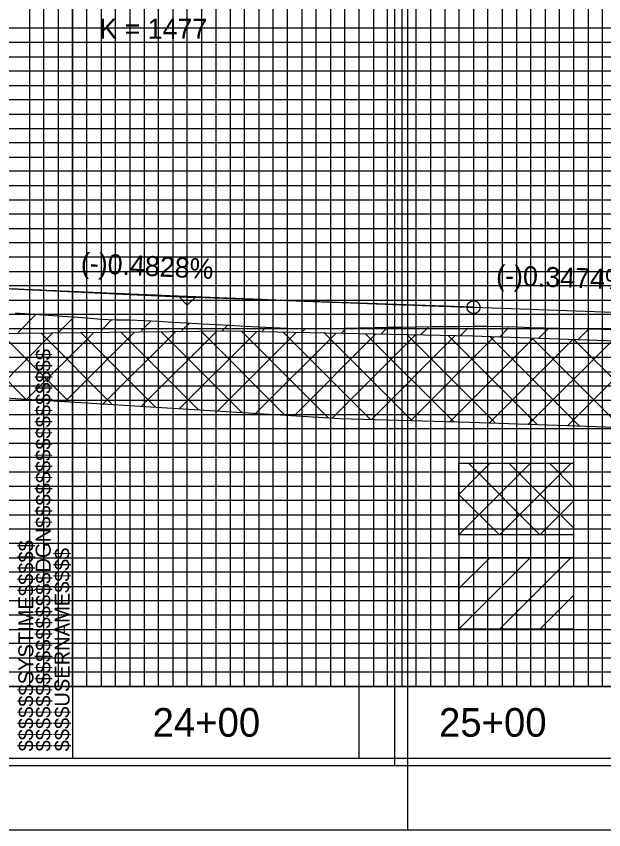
# Model space of a CAD drawing. Extents: x 2345490 to 2436403, y 465165 to 573888.
# Drawn here: x 2383070.5 to 2383275.6, y 491453 to 491737.1 of the extents above; entities that cross this region are included whole.
import ezdxf

# ---------------------------------------------------------------- set-up
doc = ezdxf.new("R2010")
doc.units = 0
for name, color, linetype in [('Old_Level_1', 7, 'Continuous'), ('Old_Level_18', 7, 'Continuous'), ('Old_Level_2', 7, 'Continuous'), ('Old_Level_40', 7, 'Continuous'), ('Old_Level_41', 7, 'Continuous'), ('Old_Level_42', 7, 'Continuous'), ('Old_Level_43', 7, 'Continuous'), ('Old_Level_5', 7, 'Continuous'), ('Old_Level_50', 7, 'Continuous'), ('Old_Level_51', 7, 'Continuous'), ('Old_Level_62', 7, 'Continuous'), ('Old_Level_63', 7, 'Continuous'), ('Prop Vertical Profile Grade', 7, 'Continuous')]:
    doc.layers.add(name, color=color, linetype=linetype)

msp = doc.modelspace()

# ---------------------------------------------------------------- linework, layer by layer
at = {"layer": 'Old_Level_1'}
for points in [[(2383070.125, 491633.55625), (2383075.125, 491633.1875), (2383080.125, 491632.81875), (2383085.125, 491632.45), (2383090.125, 491632.08125), (2383095.125, 491631.7125), (2383100.125, 491631.34375), (2383105.125, 491631.0885), (2383110.125, 491631.014), (2383115.125, 491630.83225), (2383120.125, 491630.5555), (2383125.125, 491630.27875), (2383130.125, 491630.002), (2383135.125, 491629.72525), (2383140.125, 491629.4485), (2383145.125, 491629.172), (2383150.125, 491628.89525), (2383155.125, 491628.6185), (2383160.125, 491628.34175), (2383165.125, 491628.175), (2383170.125, 491628.07075), (2383175.125, 491628.00875), (2383180.125, 491628.09875), (2383185.125, 491628.189), (2383190.125, 491628.27925), (2383195.125, 491628.36925), (2383200.125, 491628.4595), (2383205.125, 491628.5495), (2383210.125, 491628.63975), (2383215.125, 491628.73), (2383220.125, 491628.776), (2383225.125, 491628.7905), (2383230.125, 491628.805), (2383235.125, 491628.81925), (2383240.125, 491628.71075)], [(2383240.125, 491628.71075), (2383245.125, 491628.57625), (2383250.125, 491628.4415), (2383255.125, 491628.307), (2383260.125, 491628.17225), (2383265.125, 491628.03775), (2383270.125, 491627.903), (2383275.125, 491627.81575), (2383280.125, 491627.77375)]]:
    msp.add_lwpolyline(points, dxfattribs=at)
at = {"layer": 'Old_Level_18'}
msp.add_line((2383090.125, 491477.95225), (2383090.125, 491477.95225), dxfattribs=at)
msp.add_line((2383090.125, 491477.95225), (2383090.125, 491477.95225), dxfattribs=at)
for points in [[(2383190.125, 492527.95225), (2381690.125, 492527.95225), (2381690.125, 491477.95225), (2383190.125, 491477.95225)], [(2384590.125, 492527.95225), (2383090.125, 492527.95225), (2383090.125, 491477.95225), (2384590.125, 491477.95225)]]:
    msp.add_lwpolyline(points, close=True, dxfattribs=at)
at = {"layer": 'Old_Level_2'}
for p, q in [((2383030.125, 491643.77989), (2383127.3782, 491639.0849)), ((2383127.3782, 491639.0849), (2383132.87334, 491638.85683)), ((2383130.125, 491636.2023), (2383127.3782, 491639.0849)), ((2383132.87334, 491638.85683), (2383130.125, 491636.2023)), ((2383230.125, 491635.47869), (2383132.87334, 491638.85683))]:
    msp.add_line(p, q, dxfattribs=at)
msp.add_circle((2383230.125, 491635.47869), 2.25, dxfattribs=at)
at = {"layer": 'Old_Level_40'}
msp.add_line((2383090.125, 491477.95225), (2383090.125, 491477.95225), dxfattribs=at)
msp.add_line((2383090.125, 491477.95225), (2383090.125, 491477.95225), dxfattribs=at)
msp.add_line((2383090.125, 491477.95225), (2383090.125, 491477.95225), dxfattribs=at)
msp.add_line((2383090.125, 491477.95225), (2383090.125, 491477.95225), dxfattribs=at)
at = {"layer": 'Old_Level_41'}
for p, q in [((2383190.125, 491502.95225), (2381690.125, 491502.95225)), ((2384590.125, 491502.95225), (2383090.125, 491502.95225))]:
    msp.add_line(p, q, dxfattribs=at)
for points in [[(2383090.125, 492527.95225), (2383140.125, 492527.95225), (2383140.125, 491502.95225), (2383190.125, 491502.95225), (2383190.125, 492527.95225), (2383240.125, 492527.95225), (2383240.125, 491502.95225), (2383290.125, 491502.95225), (2383290.125, 492527.95225), (2383340.125, 492527.95225), (2383340.125, 491502.95225), (2383390.125, 491502.95225), (2383390.125, 492527.95225), (2383440.125, 492527.95225), (2383440.125, 491502.95225), (2383490.125, 491502.95225), (2383490.125, 492527.95225), (2383540.125, 492527.95225), (2383540.125, 491502.95225), (2383590.125, 491502.95225), (2383590.125, 492527.95225), (2383640.125, 492527.95225), (2383640.125, 491502.95225), (2383690.125, 491502.95225)], [(2383165.125, 491502.95225), (2383165.125, 492527.95225), (2383215.125, 492527.95225), (2383215.125, 491502.95225), (2383265.125, 491502.95225), (2383265.125, 492527.95225), (2383315.125, 492527.95225), (2383315.125, 491502.95225), (2383365.125, 491502.95225), (2383365.125, 492527.95225), (2383415.125, 492527.95225), (2383415.125, 491502.95225), (2383465.125, 491502.95225), (2383465.125, 492527.95225), (2383515.125, 492527.95225), (2383515.125, 491502.95225), (2383565.125, 491502.95225), (2383565.125, 492527.95225), (2383615.125, 492527.95225), (2383615.125, 491502.95225), (2383665.125, 491502.95225), (2383665.125, 492527.95225), (2383715.125, 492527.95225)], [(2383115.125, 492390.40225), (2383115.125, 491502.95225)], [(2383190.125, 491727.95225), (2381690.125, 491727.95225), (2381690.125, 491677.95225), (2383190.125, 491677.95225)], [(2384590.125, 491727.95225), (2383090.125, 491727.95225), (2383090.125, 491677.95225), (2384590.125, 491677.95225)], [(2383190.125, 491627.95225), (2381690.125, 491627.95225), (2381690.125, 491577.95225), (2383190.125, 491577.95225)], [(2384590.125, 491627.95225), (2383090.125, 491627.95225), (2383090.125, 491577.95225), (2384590.125, 491577.95225)], [(2383190.125, 491552.95225), (2381690.125, 491552.95225), (2381690.125, 491602.95225), (2383190.125, 491602.95225)], [(2384590.125, 491552.95225), (2383090.125, 491552.95225), (2383090.125, 491602.95225), (2384590.125, 491602.95225)], [(2383190.125, 491527.95225), (2381690.125, 491527.95225)], [(2384590.125, 491527.95225), (2383090.125, 491527.95225)], [(2383127.625, 491477.95225), (2383127.625, 491477.95225)]]:
    msp.add_lwpolyline(points, dxfattribs=at)
at = {"layer": 'Old_Level_42'}
for points in [[(2383040.125, 492390.40225), (2383040.125, 491502.95225), (2383090.125, 491502.95225), (2383090.125, 492390.40225)], [(2383140.125, 492390.40225), (2383140.125, 491502.95225), (2383190.125, 491502.95225)], [(2383190.125, 491652.95225), (2381690.125, 491652.95225), (2381690.125, 491702.95225), (2383190.125, 491702.95225)], [(2384590.125, 491652.95225), (2383090.125, 491652.95225), (2383090.125, 491702.95225), (2384590.125, 491702.95225)]]:
    msp.add_lwpolyline(points, dxfattribs=at)
at = {"layer": 'Old_Level_43'}
for points in [[(2383145.125, 492527.95225), (2383145.125, 491502.95225), (2383150.125, 491502.95225), (2383150.125, 492527.95225)], [(2383155.125, 492527.95225), (2383155.125, 491502.95225), (2383160.125, 491502.95225), (2383160.125, 492527.95225)], [(2383170.125, 492527.95225), (2383170.125, 491502.95225), (2383175.125, 491502.95225), (2383175.125, 492527.95225)], [(2383180.125, 492527.95225), (2383180.125, 491502.95225), (2383185.125, 491502.95225), (2383185.125, 492527.95225)], [(2383195.125, 492527.95225), (2383195.125, 491502.95225), (2383200.125, 491502.95225), (2383200.125, 492527.95225)], [(2383205.125, 492527.95225), (2383205.125, 491502.95225), (2383210.125, 491502.95225), (2383210.125, 492527.95225)], [(2383220.125, 492527.95225), (2383220.125, 491502.95225), (2383225.125, 491502.95225), (2383225.125, 492527.95225)], [(2383230.125, 492527.95225), (2383230.125, 491502.95225), (2383235.125, 491502.95225), (2383235.125, 492527.95225)], [(2383245.125, 492527.95225), (2383245.125, 491502.95225), (2383250.125, 491502.95225), (2383250.125, 492527.95225)], [(2383255.125, 492527.95225), (2383255.125, 491502.95225), (2383260.125, 491502.95225), (2383260.125, 492527.95225)], [(2383270.125, 492527.95225), (2383270.125, 491502.95225), (2383275.125, 491502.95225), (2383275.125, 492527.95225)], [(2383075.125, 492390.40225), (2383075.125, 491502.95225)], [(2383075.125, 491502.95225), (2383080.125, 491502.95225), (2383080.125, 492390.40225)], [(2383085.125, 492390.40225), (2383085.125, 491502.95225), (2383095.125, 491502.95225), (2383095.125, 492390.40225)], [(2383100.125, 492390.40225), (2383100.125, 491502.95225), (2383105.125, 491502.95225), (2383105.125, 492390.40225)], [(2383110.125, 492390.40225), (2383110.125, 491502.95225), (2383120.125, 491502.95225), (2383120.125, 492390.40225)], [(2383125.125, 492390.40225), (2383125.125, 491502.95225), (2383130.125, 491502.95225), (2383130.125, 492390.40225)], [(2383135.125, 492390.40225), (2383135.125, 491502.95225), (2383145.125, 491502.95225)], [(2383140.125, 491732.95225), (2381740.125, 491732.95225), (2381740.125, 491722.95225), (2383140.125, 491722.95225)], [(2384540.125, 491732.95225), (2383140.125, 491732.95225), (2383140.125, 491722.95225), (2384540.125, 491722.95225)], [(2383140.125, 491717.95225), (2381740.125, 491717.95225), (2381740.125, 491712.95225), (2383140.125, 491712.95225)], [(2384540.125, 491717.95225), (2383140.125, 491717.95225), (2383140.125, 491712.95225), (2384540.125, 491712.95225)], [(2383140.125, 491707.95225), (2381740.125, 491707.95225)], [(2384540.125, 491707.95225), (2383140.125, 491707.95225)], [(2381740.125, 491697.95225), (2383140.125, 491697.95225)], [(2383140.125, 491697.95225), (2384540.125, 491697.95225)], [(2383140.125, 491692.95225), (2381740.125, 491692.95225), (2381740.125, 491687.95225), (2383140.125, 491687.95225)], [(2384540.125, 491692.95225), (2383140.125, 491692.95225), (2383140.125, 491687.95225), (2384540.125, 491687.95225)], [(2383140.125, 491682.95225), (2381740.125, 491682.95225)], [(2384540.125, 491682.95225), (2383140.125, 491682.95225)], [(2381740.125, 491672.95225), (2383140.125, 491672.95225)], [(2383140.125, 491672.95225), (2384540.125, 491672.95225)], [(2383140.125, 491667.95225), (2381740.125, 491667.95225), (2381740.125, 491662.95225), (2383140.125, 491662.95225)], [(2384540.125, 491667.95225), (2383140.125, 491667.95225), (2383140.125, 491662.95225), (2384540.125, 491662.95225)], [(2383140.125, 491657.95225), (2381740.125, 491657.95225), (2381740.125, 491647.95225), (2383140.125, 491647.95225)], [(2384540.125, 491657.95225), (2383140.125, 491657.95225), (2383140.125, 491647.95225), (2384540.125, 491647.95225)], [(2383140.125, 491642.95225), (2381740.125, 491642.95225), (2381740.125, 491637.95225), (2383140.125, 491637.95225)], [(2384540.125, 491642.95225), (2383140.125, 491642.95225), (2383140.125, 491637.95225), (2384540.125, 491637.95225)], [(2383140.125, 491632.95225), (2381740.125, 491632.95225), (2381740.125, 491622.95225), (2383140.125, 491622.95225)], [(2384540.125, 491632.95225), (2383140.125, 491632.95225), (2383140.125, 491622.95225), (2384540.125, 491622.95225)], [(2383140.125, 491617.95225), (2381740.125, 491617.95225), (2381740.125, 491612.95225), (2383140.125, 491612.95225)], [(2384540.125, 491617.95225), (2383140.125, 491617.95225), (2383140.125, 491612.95225), (2384540.125, 491612.95225)], [(2383140.125, 491607.95225), (2381740.125, 491607.95225), (2381740.125, 491597.95225), (2383140.125, 491597.95225)], [(2384540.125, 491607.95225), (2383140.125, 491607.95225), (2383140.125, 491597.95225), (2384540.125, 491597.95225)], [(2383140.125, 491592.95225), (2381740.125, 491592.95225), (2381740.125, 491587.95225), (2383140.125, 491587.95225)], [(2384540.125, 491592.95225), (2383140.125, 491592.95225), (2383140.125, 491587.95225), (2384540.125, 491587.95225)], [(2383140.125, 491582.95225), (2381740.125, 491582.95225), (2381740.125, 491572.95225), (2383140.125, 491572.95225)], [(2384540.125, 491582.95225), (2383140.125, 491582.95225), (2383140.125, 491572.95225), (2384540.125, 491572.95225)], [(2383140.125, 491567.95225), (2381740.125, 491567.95225), (2381740.125, 491562.95225), (2383140.125, 491562.95225)], [(2384540.125, 491567.95225), (2383140.125, 491567.95225), (2383140.125, 491562.95225), (2384540.125, 491562.95225)], [(2383140.125, 491557.95225), (2381740.125, 491557.95225), (2381740.125, 491547.95225), (2383140.125, 491547.95225)], [(2384540.125, 491557.95225), (2383140.125, 491557.95225), (2383140.125, 491547.95225), (2384540.125, 491547.95225)], [(2383140.125, 491542.95225), (2381740.125, 491542.95225), (2381740.125, 491537.95225), (2383140.125, 491537.95225)], [(2384540.125, 491542.95225), (2383140.125, 491542.95225), (2383140.125, 491537.95225), (2384540.125, 491537.95225)], [(2383140.125, 491532.95225), (2381740.125, 491532.95225), (2381740.125, 491522.95225), (2383140.125, 491522.95225)], [(2384540.125, 491532.95225), (2383140.125, 491532.95225), (2383140.125, 491522.95225), (2384540.125, 491522.95225)], [(2383140.125, 491517.95225), (2381740.125, 491517.95225), (2381740.125, 491512.95225), (2383140.125, 491512.95225)], [(2384540.125, 491517.95225), (2383140.125, 491517.95225), (2383140.125, 491512.95225), (2384540.125, 491512.95225)], [(2383140.125, 491507.95225), (2381740.125, 491507.95225)], [(2384540.125, 491507.95225), (2383140.125, 491507.95225)]]:
    msp.add_lwpolyline(points, dxfattribs=at)
at = {"layer": 'Old_Level_5'}
for p, q in [((2383070.97543, 491626.56647), (2383077.4445, 491633.03553)), ((2383085.4583, 491626.9072), (2383090.62474, 491632.07364)), ((2383099.94116, 491627.24793), (2383103.86551, 491631.17227)), ((2383114.15767, 491627.3223), (2383117.32488, 491630.48951)), ((2383128.2998, 491627.3223), (2383130.88777, 491629.91027)), ((2383142.44194, 491627.3223), (2383144.2882, 491629.16856)), ((2383156.46194, 491627.20016), (2383157.68883, 491628.42706)), ((2383211.72953, 491625.89922), (2383214.21199, 491628.38168)), ((2383225.44921, 491625.47676), (2383228.28438, 491628.31193)), ((2383239.14736, 491625.03278), (2383242.35677, 491628.24218)), ((2383051.15242, 491626.05368), (2383073.8457, 491603.3604)), ((2383060.86816, 491604.16012), (2383083.11935, 491626.41131)), ((2383065.13809, 491626.21014), (2383088.91656, 491602.43168)), ((2383074.18939, 491603.33922), (2383097.42149, 491626.57132)), ((2383079.12376, 491626.36661), (2383103.98741, 491601.50296)), ((2383087.51063, 491602.51832), (2383111.72364, 491626.73133)), ((2383093.10943, 491626.52308), (2383119.05827, 491600.57424)), ((2383100.83186, 491601.69741), (2383126.02578, 491626.89133)), ((2383107.0951, 491626.67954), (2383134.12913, 491599.64551)), ((2383114.15309, 491600.87651), (2383140.32792, 491627.05134)), ((2383121.08077, 491626.83601), (2383149.19999, 491598.71679)), ((2383127.47432, 491600.05561), (2383154.32117, 491626.90246)), ((2383135.06644, 491626.99248), (2383164.27084, 491597.78807)), ((2383140.79556, 491599.2347), (2383168.1782, 491626.61735)), ((2383149.19308, 491627.00797), (2383179.3417, 491596.85935)), ((2383154.11679, 491598.4138), (2383182.03523, 491626.33224)), ((2383163.63231, 491626.71088), (2383194.02711, 491596.31607)), ((2383167.43802, 491597.5929), (2383195.89225, 491626.04713)), ((2383170.2898, 491626.88589), (2383171.31145, 491627.90754)), ((2383178.07153, 491626.41379), (2383208.56646, 491595.91886)), ((2383180.75925, 491596.772), (2383209.74928, 491625.76202)), ((2383184.11767, 491626.57162), (2383185.45183, 491627.90578)), ((2383192.51075, 491626.1167), (2383223.10581, 491595.52165)), ((2383194.43434, 491596.30495), (2383223.60631, 491625.47691)), ((2383197.94553, 491626.25735), (2383199.81839, 491628.13021)), ((2383206.94998, 491625.81962), (2383237.71045, 491595.05914)), ((2383221.3892, 491625.52253), (2383252.35668, 491594.55505)), ((2383252.81474, 491624.55802), (2383256.38571, 491628.12898)), ((2383266.48212, 491624.08326), (2383270.21991, 491627.82105)), ((2383208.20039, 491595.92886), (2383237.35815, 491625.08662)), ((2383221.96644, 491595.55278), (2383251.02553, 491624.61187)), ((2383235.68467, 491595.12887), (2383264.69291, 491624.13711)), ((2383235.91719, 491625.13667), (2383267.00291, 491594.05095)), ((2383249.35625, 491594.65832), (2383278.3603, 491623.66236)), ((2383250.56825, 491624.62775), (2383281.64915, 491593.54685)), ((2383263.02784, 491594.18776), (2383292.02768, 491623.1876)), ((2383265.21931, 491624.11883), (2383296.29538, 491593.04276)), ((2383225.01945, 491570.10888), (2383235.87731, 491580.96674)), ((2383225.01945, 491555.96674), (2383250.01945, 491580.96674)), ((2383228.30372, 491580.96674), (2383253.30372, 491555.96674)), ((2383239.16158, 491555.96674), (2383264.16158, 491580.96674)), ((2383242.44585, 491580.96674), (2383265.01945, 491558.39315)), ((2383256.58799, 491580.96674), (2383265.01945, 491572.53529)), ((2383225.01945, 491570.10888), (2383239.16158, 491555.96674)), ((2383253.30372, 491555.96674), (2383265.01945, 491567.68247)), ((2383225.01945, 491555.96674), (2383225.01945, 491555.96674)), ((2383225.01945, 491537.19493), (2383235.87731, 491548.05279)), ((2383225.01945, 491523.05279), (2383250.01945, 491548.05279)), ((2383239.16158, 491523.05279), (2383264.16158, 491548.05279)), ((2383253.30372, 491523.05279), (2383265.01945, 491534.76852)), ((2383225.01945, 491523.05279), (2383225.01945, 491523.05279))]:
    msp.add_line(p, q, dxfattribs=at)
msp.add_lwpolyline([(2382934.83795, 491597.73858), (2383032.62499, 491604.97631), (2383047.62499, 491604.97631), (2383183.48336, 491596.60422), (2383228.76328, 491595.36718), (2383526.4582, 491585.12107), (2383527.68499, 491615.09754), (2383504.06829, 491615.8222), (2383229.77783, 491625.35003), (2383144.70493, 491627.10041), (2383030.41861, 491625.82181), (2382939.67787, 491624.39126), (2382935.12499, 491599.31925)], dxfattribs=at)
for points in [[(2383225.01945, 491580.96674), (2383265.01945, 491580.96674), (2383265.01945, 491555.96674), (2383225.01945, 491555.96674)], [(2383225.01945, 491548.05279), (2383265.01945, 491548.05279), (2383265.01945, 491523.05279), (2383225.01945, 491523.05279)]]:
    msp.add_lwpolyline(points, close=True, dxfattribs=at)
at = {"layer": 'Old_Level_50'}
for points in [[(2383202.625, 492530.50225), (2381536.125, 492530.50225), (2381536.125, 491475.40225), (2383202.625, 491475.40225)], [(2384602.625, 492530.50225), (2382936.125, 492530.50225), (2382936.125, 491475.40225), (2384602.625, 491475.40225)]]:
    msp.add_lwpolyline(points, close=True, dxfattribs=at)
at = {"layer": 'Old_Level_51'}
for points in [[(2383207.125, 492552.95225), (2381523.125, 492552.95225), (2381523.125, 491452.95225), (2383207.125, 491452.95225)], [(2384607.125, 492552.95225), (2382923.125, 492552.95225), (2382923.125, 491452.95225), (2384607.125, 491452.95225)]]:
    msp.add_lwpolyline(points, close=True, dxfattribs=at)
at = {"layer": 'Old_Level_63'}
msp.add_line((2381740.125, 491502.95225), (2383587.28325, 491502.95225), dxfattribs=at)
at = {"layer": 'Prop Vertical Profile Grade'}
msp.add_line((2383230.125, 491635.47869), (2383504.375, 491625.9523), dxfattribs=at)
msp.add_spline([(2383030.125, 491643.77989), (2383034.125, 491643.58732), (2383038.125, 491643.39585), (2383042.125, 491643.20545), (2383046.125, 491643.01614), (2383050.125, 491642.82791), (2383054.125, 491642.64076), (2383058.125, 491642.4547), (2383062.125, 491642.26972), (2383066.125, 491642.08582), (2383070.125, 491641.90301), (2383074.125, 491641.72128), (2383078.125, 491641.54063), (2383082.125, 491641.36107), (2383086.125, 491641.18259), (2383090.125, 491641.00519), (2383094.125, 491640.82888), (2383098.125, 491640.65365), (2383102.125, 491640.4795), (2383106.125, 491640.30643), (2383110.125, 491640.13445), (2383114.125, 491639.96355), (2383118.125, 491639.79374), (2383122.125, 491639.62501), (2383126.125, 491639.45736), (2383130.125, 491639.29079), (2383134.125, 491639.12531), (2383138.125, 491638.96091), (2383142.125, 491638.7976), (2383146.125, 491638.63536), (2383150.125, 491638.47421), (2383154.125, 491638.31415), (2383158.125, 491638.15516), (2383162.125, 491637.99726), (2383166.125, 491637.84045), (2383170.125, 491637.68471), (2383174.125, 491637.53006), (2383178.125, 491637.37649), (2383182.125, 491637.22401), (2383186.125, 491637.07261), (2383190.125, 491636.92229), (2383194.125, 491636.77306), (2383198.125, 491636.6249), (2383202.125, 491636.47784), (2383206.125, 491636.33185), (2383210.125, 491636.18695), (2383214.125, 491636.04313), (2383218.125, 491635.90039), (2383222.125, 491635.75874), (2383226.125, 491635.61817), (2383230.125, 491635.47869)], degree=3, dxfattribs=at)

# ---------------------------------------------------------------- texts
at = {"layer": 'Old_Level_2'}
msp.add_text('K = 1477', height=7.000001, dxfattribs=at).set_placement((2383099.41231, 491729.27573))
for s, rotation, p in [('(-)0.4828%', 357.2361426, (2383092.87489, 491647.54714)), ('(-)0.3474%', 358.0105657, (2383237.91716, 491643.19607))]:
    msp.add_text(s, height=7, rotation=rotation, dxfattribs=at).set_placement(p)
at = {"layer": 'Old_Level_41'}
for s, p in [('$$$$$$$$$$$$$$$$DGN$$$$$$$$$$$$$$$$', (2383082.475, 491480.31475)), ('$$$$$$SYSTIME$$$$$', (2383076.425, 491480.31475)), ('$$$$USERNAME$$$$', (2383089.05, 491480.32725))]:
    msp.add_text(s, height=5.25, rotation=90, dxfattribs=at).set_placement(p)
at = {"layer": 'Old_Level_62'}
for s, p in [('24+00', (2383118.057, 491485.45225)), ('25+00', (2383218.057, 491485.45225))]:
    msp.add_text(s, height=10.000001, dxfattribs=at).set_placement(p)

doc.saveas('drawing.dxf')
